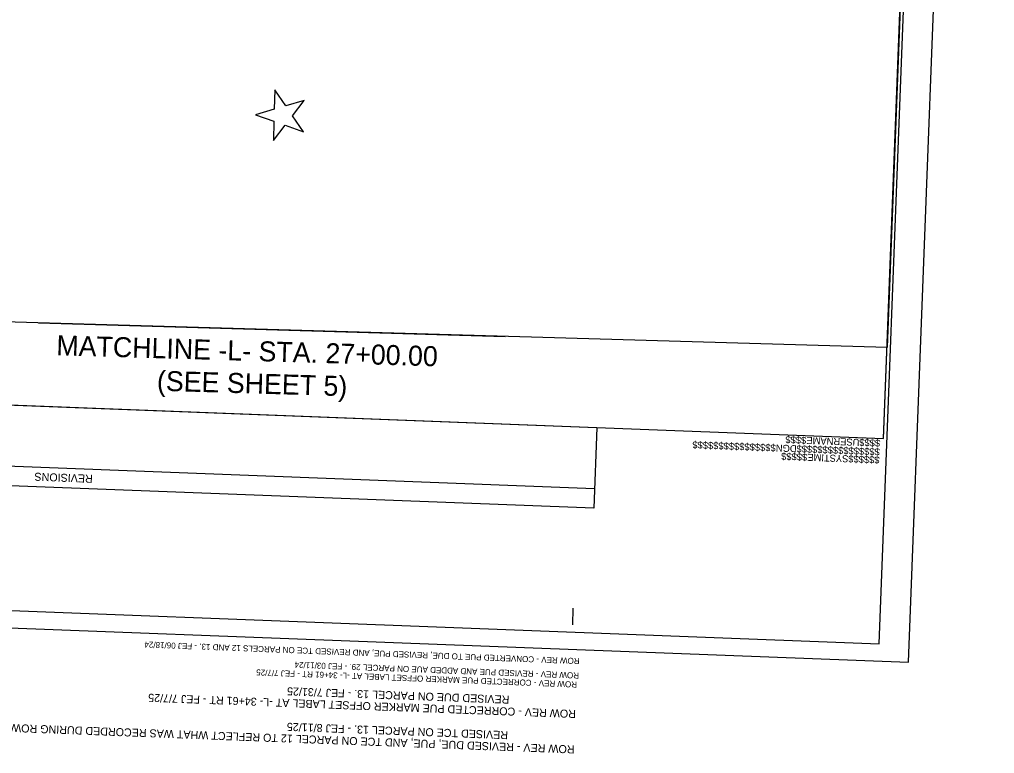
# Model space of a CAD drawing. Extents: x 2097096 to 2098260, y 686401 to 688363.
# Drawn here: x 2097529 to 2098260, y 686401 to 686951 of the extents above; entities that cross this region are included whole.
import ezdxf

# ---------------------------------------------------------------- set-up
doc = ezdxf.new("R2010")
doc.units = 0
for name, color, linetype in [('Matchline', 7, 'Continuous'), ('Matchline Text', 7, 'Continuous'), ('Prop RDY Traffic Signal CELL', 7, 'Continuous'), ('Sheet Block Revision CELL', 7, 'Continuous'), ('Sheet Layout Plan Border', 7, 'Continuous'), ('Sheet Plan CELL', 7, 'Continuous'), ('Sheet Plot Border Inside CELL', 7, 'Continuous'), ('Sheet Plot Border Outside CELL', 7, 'Continuous'), ('Sheet Profile CELL', 7, 'Continuous'), ('Sheet Profile Grid Major CELL', 7, 'Continuous')]:
    doc.layers.add(name, color=color, linetype=linetype)

msp = doc.modelspace()

# ---------------------------------------------------------------- linework, layer by layer
at = {"layer": 'Matchline'}
msp.add_line((2097543.06, 686723.93), (2097892.91, 686713.76), dxfattribs=at)
at = {"layer": 'Prop RDY Traffic Signal CELL'}
msp.add_lwpolyline([(2097728.45, 686886.55), (2097720.26, 686898.52), (2097719.85, 686884.02), (2097705.9, 686879.92), (2097719.6, 686875.03), (2097719.19, 686860.51), (2097728.06, 686872.02), (2097741.73, 686867.14), (2097733.53, 686879.13), (2097742.4, 686890.65), (2097728.45, 686886.55)], dxfattribs=at)
at = {"layer": 'Sheet Block Revision CELL'}
msp.add_line((2097959.97, 686599.52), (2097169.9, 686629.82), dxfattribs=at)
msp.add_lwpolyline([(2097959.41, 686584.98), (2097169.34, 686615.28), (2097171.66, 686675.79), (2097961.73, 686645.48)], close=True, dxfattribs=at)
at = {"layer": 'Sheet Layout Plan Border'}
msp.add_lwpolyline([(2098179.19, 686705.44), (2097129.59, 686735.95), (2097177.17, 687976.48), (2097364.33, 687969.3), (2097368.7, 688083.22), (2098230.76, 688050.16)], close=True, dxfattribs=at)
at = {"layer": 'Sheet Plot Border Inside CELL'}
msp.add_lwpolyline([(2098173.22, 686483.26), (2098237.09, 688148.54), (2097182.76, 688188.97), (2097118.9, 686523.7)], close=True, dxfattribs=at)
at = {"layer": 'Sheet Plot Border Outside CELL'}
msp.add_lwpolyline([(2098195.16, 686469.41), (2098259.69, 688152.17), (2097160.5, 688194.33), (2097095.97, 686511.57)], close=True, dxfattribs=at)
at = {"layer": 'Sheet Profile CELL'}
for p, q in [((2098176.58, 686637.25), (2098234.06, 688136.14)), ((2098176.58, 686637.25), (2098176.58, 686637.25)), ((2098176.58, 686637.25), (2098176.58, 686637.25)), ((2098176.58, 686637.25), (2098176.58, 686637.25)), ((2098176.58, 686637.25), (2098176.58, 686637.25)), ((2098176.58, 686637.25), (2098176.58, 686637.25)), ((2098176.58, 686637.25), (2098176.58, 686637.25)), ((2098176.58, 686637.25), (2098176.58, 686637.25)), ((2097943.55, 686497.57), (2097944.03, 686510.06))]:
    msp.add_line(p, q, dxfattribs=at)
msp.add_lwpolyline([(2097184.83, 688176.38), (2097127.35, 686677.48), (2098176.58, 686637.25), (2098234.06, 688136.14)], close=True, dxfattribs=at)
msp.add_lwpolyline([(2098178.01, 686674.72), (2098178.01, 686674.72)], dxfattribs=at)
at = {"layer": 'Sheet Profile Grid Major CELL'}
msp.add_line((2098151.59, 686638.2), (2098151.59, 686638.2), dxfattribs=at)

# ---------------------------------------------------------------- texts
at = {"layer": 'Matchline Text'}
for s, p in [('MATCHLINE -L- STA. 27+00.00', (2097556.42, 686699.57)), ('(SEE SHEET 5)', (2097631.79, 686673))]:
    msp.add_text(s, height=15, rotation=358.33483, dxfattribs=at).set_placement(p)
at = {"layer": 'Sheet Block Revision CELL'}
for s, height, p in [('REVISIONS', 6, (2097583.94, 686609.89)), ('ROW REV - CONVERTED PUE TO DUE, REVISED PUE, AND REVISED TCE ON PARCELS 12 AND 13. - FEJ 06/18/24', 4.5, (2097948.8, 686472.47)), ('ROW REV - REVISED PUE AND ADDED AUE ON PARCEL 29. - FEJ 03/11/24', 4.5, (2097948.38, 686461.65)), ('ROW REV - CORRECTED PUE MARKER OFFSET LABEL AT -L- 34+61 RT - FEJ 7/7/25', 4.5, (2097946.89, 686454.91)), ('ROW REV - CORRECTED PUE MARKER OFFSET LABEL AT -L- 34+61 RT - FEJ 7/7/25', 6, (2097946.07, 686433.56)), (' REVISED DUE ON PARCEL 13. - FEJ 7/31/25', 6, (2097898.44, 686444.21)), ('ROW REV - REVISED DUE, PUE, AND TCE ON PARCEL 12 TO REFLECT WHAT WAS RECORDED DURING ROW ACQUISITION. - FEJ 8/11/25', 6, (2097945.05, 686406.97)), (' REVISED TCE ON PARCEL 13. - FEJ 8/11/25', 6, (2097897.42, 686417.61))]:
    msp.add_text(s, height=height, rotation=177.8037, dxfattribs=at).set_placement(p)
at = {"layer": 'Sheet Plan CELL'}
for s, p in [('$$$$USERNAME$$$$', (2098174.16, 686636.25)), ('$$$$$$$$$$$$$$$$DGN$$$$$$$$$$$$$$$$', (2098173.92, 686629.7)), ('$$$$$$SYSTIME$$$$$', (2098173.71, 686623.63))]:
    msp.add_text(s, height=5.25, rotation=177.8037, dxfattribs=at).set_placement(p)

doc.saveas('drawing.dxf')
